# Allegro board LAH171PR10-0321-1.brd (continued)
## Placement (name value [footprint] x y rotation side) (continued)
PJP1  PAD-OPEN1x1m  [JUMP_43X39]  182.8 102.44 0 top
PJP2  PAD-OPEN1x1m  [JUMP_43X39]  184.01 98.56 0 top
PJP3  -  [JUMP_43X79]  227.9 90.05 180 top
PJP5  -  [JUMP_43X79]  31.19 114.13 90 top
PJP6  PAD-OPEN1x1m  [JUMP_43X39]  31.23 117.45 0 bottom
PJP8  PAD-OPEN 1x3m  [JUMP_43X118]  70.24 100.86 90 bottom
PJP12  PAD-OPEN1x1m  [JUMP_43X39]  145.02 131.58 0 top
PJP14  PAD-OPEN1x2m  [JUMP_43X79]  284.92 29.2 270 top
PJP17  PAD-OPEN1x2m  [JUMP_43X79]  288.54 76 270 top
PJP18  PAD-OPEN1x1m  [JUMP_43X39]  282.39 75.83 180 top
PJP19  PAD-OPEN1x1m  [JUMP_43X39]  293.67 59.38 0 top
PJP20  PAD-OPEN1x1m  [JUMP_43X39]  254.82 89.72 90 top
PJP22  PAD-OPEN1x1m  [JUMP_43X39]  253.23 99.34 270 top
PJP31  -  [JUMP_43X79]  258.02 43.4 180 top
PJP32  PAD-OPEN1x1m  [JUMP_43X39]  259.27 33.02 90 top
PJP33  PAD-OPEN1x1m  [JUMP_43X39]  257.2 36.44 90 top
PJP34  PAD-OPEN1x2m  [JUMP_43X79]  251.66 38.5 180 top
PJP35  PAD-OPEN1x1m  [JUMP_43X39]  195.72 40.64 180 top
PJP36  PAD-OPEN1x2m  [JUMP_43X79]  265.93 43.89 270 bottom
PJP37  PAD-OPEN1x1m  [JUMP_43X39]  255.94 80.35 180 top
PJP38  PAD-OPEN1x1m  [JUMP_43X39]  263.71 49.16 0 bottom
PJP39  PAD-OPEN1x3m  [JUMP_43X118]  255.27 50.41 270 top
PJP40  PAD-OPEN1x2m  [JUMP_43X79]  264.9 39.3 180 top
PJP41  PAD-OPEN1x3m  [JUMP_43X118]  256.98 86.6 270 bottom
PJP42  PAD-OPEN1x1m  [JUMP_43X39]  263.79 35.25 180 top
PJP100  PAD-OPEN 1x2m~D  [JUMP_43X79]  251.39 45.67 180 bottom
PJP101  PAD-OPEN 1x2m~D  [JUMP_43X79]  200.52 31.93 180 bottom
PJP102  -  [JUMP_43X118]  243.94 56.4 180 top
PJP103  -  [JUMP_43X118]  207.89 36.56 270 top
PJP200  -  [JUMP_43X118]  160.65 41.18 90 bottom
PJP201  -  [JUMP_43X39]  173.93 33.03 180 top
PJP202  PAD-OPEN 1x2m~D  [JUMP_43X79]  183 32.07 90 top
PJP301  PAD-OPEN 1x2m~D  [JUMP_43X79]  199.07 83.34 90 top
PJP302  -  [JUMP_43X118]  203.28 90.31 0 top
PJP401  -  [JUMP_43X79]  190.98 91.57 180 bottom
PJP403  PAD-OPEN1x1m  [JUMP_43X39]  201.78 95.46 180 bottom
PJP501  PAD-OPEN1x1m  [JUMP_43X39]  227.06 71.45 0 top
PJP502  PAD-OPEN1x1m  [JUMP_43X39]  235.39 76.17 270 top
PJP503  PAD-OPEN1x1m  [JUMP_43X39]  270.36 67.93 90 bottom
PJP504  PAD-OPEN1x1m  [JUMP_43X39]  270.47 64.07 0 bottom
PJP505  PAD-OPEN1x1m  [JUMP_43X39]  152.23 37.33 180 top
PJP506  PAD-OPEN1x1m  [JUMP_43X39]  144.93 37.58 90 top
PJP700  PAD-OPEN 4x4m  [JUMP_43X118-NPM]  90.47 41.05 0 bottom
PJP701  -  [JUMP_43X118]  147.72 116.99 0 top
PJP1604  -  [JUMP_43X79]  260.43 43.38 0 top
PJPA1  -  [JUMP_43X118]  200.4 128.43 90 top
PJPDC1  CVILU_CI0805M1HRC-NH  [CVILU_CI0805M1HRC-NH_5P-T]  66.08 126.47 270 bottom
PJPT1  -  [JUMP_43X118]  88.18 97.29 180 bottom
PL1  FBMJ4516HS720NT_2P  [TAIYO_FBMJ4516HS720NT_2P]  156.84 38.62 90 bottom
PL2  FBMJ4516HS720NT_2P  [TAIYO_FBMJ4516HS720NT_2P]  154.43 38.62 90 bottom
PL3  BLM15AG102SN1D_2P  [MURAT_BLM15AG102SN1D_2P]  50.99 124.24 90 top
PL4  -  [5A_Z80_0805_2P]  68.87 122.44 0 bottom
PL5  -  [5A_Z80_0805_2P]  68.87 124.22 0 bottom
PL100  1.5UH_9A_20%_7X7X3_M  [L_7X7X3_M_2P]  245.87 51.87 90 bottom
PL101  1.5UH_9A_20%_7X7X3_M  [L_7X7X3_M_2P]  207.55 31.72 90 bottom
PL201  1UH_11A_20%_7X7X3_M  [L_7X7X3_M_2P]  169.1 38.14 270 bottom
PL301  0.68UH_7.9A_20%_5X5X3_M  [L_5X5X3_M_2P]  201.54 84.51 90 bottom
PL402  1UH_PCMB042T-1R0MS_4.5A_20%  [CYNTE_PCMB042T-1R0MS_2P]  193.1 98.44 270 bottom
PL501  1UH_1277AS-H-1R0N-P2_3.3A_30%  [MAG_MLV-FY12N1R0M-O1L_2P]  229.01 77.67 0 top
PL700  1UH_PCMB051H-1R0MS_8A_20%  [CYNTE_PCMB051H-1R0MS_2P]  88.82 41.1 0 bottom
PL701  1UH_MMD-10DZ-1R0M-X1A_18A_20%  [MAG_MMD-10DZ-1R0M-X1A_2P]  108.53 41.1 270 bottom
PL800  5A_Z80_20M_0805_2P  [TAI-T_HCB2012KF-121T50_2P]  21.39 95.29 270 top
PL801  5A_Z80_20M_0805_2P  [TAI-T_HCB2012KF-121T50_2P]  23.17 95.29 270 top
PLA1  0.47UH_MMD05CZR47M_12A_20%  [MAG_MMD05CZR47M_4P]  197.7 109.72 180 bottom
PLH1  0.15UH_NA__36A_20%  [L_7X7X4_M]  158.21 120.15 180 bottom
PLH2  0.15UH_NA__36A_20%  [L_7X7X4_M]  171.15 120.21 180 bottom
PLH3  0.15UH_NA__36A_20%  [L_7X7X4_M]  181.58 120.25 180 bottom
PLH4  0.15UH_NA__36A_20%  [L_7X7X4_M]  187.93 122.06 270 bottom
PLH11  -  [5A_Z80_0805_2P]  150.16 124.27 0 top
PLH12  -  [5A_Z80_0805_2P]  149.64 120.6 0 top
PLH13  -  [5A_Z80_0805_2P]  149.64 122.44 0 top
PLT1  0.15UH_NA__36A_20%  [L_7X7X4_M]  107.54 85.59 0 bottom
PQ1  L2N7002DW1T1G 2N SC88-6  [DMN65D8LDW-7_SOT363-6]  73.09 115.72 270 top
PQ2  -  [FDV301N-G_SOT23-3]  52.23 118.69 270 top
PQ3  -  [MMST3904-7-F_SOT323-3]  50.28 117.93 90 top
PQ4  EMZB08P03V_EDFN3X3-8-5  [FDMC6679AZ_MLP8-5]  75.37 122.21 270 bottom
PQ5  AO3409 P-CHANNEL SOT-23  [AO3409_SOT23-3]  76.58 119.73 180 top
PQ6  2N7002KW 1N SOT323-3  [DMN65D8LW-7_SOT323-3]  103.63 127.64 0 top
PQ7  2N7002KW 1N SOT323-3  [DMN65D8LW-7_SOT323-3]  73.07 121.79 0 top
PQ8  2N7002KW 1N SOT323-3  [DMN65D8LW-7_SOT323-3]  103.56 128.98 180 top
PQ9  EMZB08P03V_P_DFN33-8-5  [FDMC6679AZ_MLP8-5]  72.51 124.19 90 bottom
PQ10  L2N7002DW1T1G 2N SC88-6  [DMN65D8LDW-7_SOT363-6]  98.86 130.61 90 top
PQ11  AO3409 P-CHANNEL SOT-23  [AO3409_SOT23-3]  96.02 134.64 270 top
PQ12  2N7002KW 1N SOT323-3  [DMN65D8LW-7_SOT323-3]  101 134.83 90 top
PQ13  -  [L2N7002WT1G_SC70-3]  35.24 125.48 180 top
PQ700  AON6354_N_DFN56-8-5  [Q_N_DFN56-8-5]  96.92 32.99 90 bottom
PQ701  AOE6936_DFN5X6E8-10  [AOE6930_DFN5X6E8-10]  115.37 30.93 90 top
PQ702  EMZB08P03V_EDFN3X3-8-5  [FDMC6679AZ_MLP8-5]  113.76 38.93 0 top
PQ703  2N7002KW 1N SOT323-3  [DMN65D8LW-7_SOT323-3]  141.07 33.91 90 top
PQ704  AON6354_N_DFN56-8-5  [Q_N_DFN56-8-5]  101.67 42.84 270 bottom
PQ800  EMZB08P03V_P_DFN33-8-5  [FDMC6679AZ_MLP8-5]  71.03 125.22 0 top
PQ801  EMZB08P03V_EDFN3X3-8-5  [FDMC6679AZ_MLP8-5]  76.05 123.51 0 top
PQ802  L2N7002DW1T1G 2N SC88-6  [DMN65D8LDW-7_SOT363-6]  102.09 71.2 0 top
PQ803  AO3409 P-CHANNEL SOT-23  [AO3409_SOT23-3]  96.4 71.3 270 top
PQ804  L2N7002DW1T1G 2N SC88-6  [DMN65D8LDW-7_SOT363-6]  107.88 75.4 270 top
PQ805  AO3409 P-CHANNEL SOT-23  [AO3409_SOT23-3]  110.97 71.51 270 top
PQ806  L2N7002DW1T1G 2N SC88-6  [DMN65D8LDW-7_SOT363-6]  110.72 76.59 0 top
PQ807  2N7002KW 1N SOT323-3  [DMN65D8LW-7_SOT323-3]  106.55 73.54 270 top
PQ808  L2N7002DW1T1G 2N SC88-6  [DMN66D0LDW-7_SOT363-6]  116.25 77.04 0 top
PQ809  L2N7002DW1T1G 2N SC88-6  [DMN66D0LDW-7_SOT363-6]  106.42 71.15 270 top
PQ810  L2N7002DW1T1G 2N SC88-6  [DMN66D0LDW-7_SOT363-6]  115.12 78.86 90 top
PQ811  L2N7002DW1T1G 2N SC88-6  [DMN66D0LDW-7_SOT363-6]  115 74.96 270 top
PQ812  2N7002KW 1N SOT323-3  [DMN65D8LW-7_SOT323-3]  111.95 74.75 90 top
PQ813  L2N7002DW1T1G 2N SC88-6  [DMN65D8LDW-7_SOT363-6]  108.96 77.15 90 top
PQ814  2N7002KW 1N SOT323-3  [DMN65D8LW-7_SOT323-3]  96.52 75.45 90 top
PQ3000  -  [L2N7002DW1T1G_SC88-6]  43.56 122.01 270 top
PR1  100K_0201_5%  [R_0201]  135.23 38.47 0 top
PR2  1K_0201_1%  [R_0201]  292.92 62.95 90 bottom
PR3  0_0402_5%  [R_0402]  50.1 124.2 90 top
PR4  2.2K_0201_5%  [R_0201]  47.81 124.11 90 top
PR5  33_0402_5%  [R_0402]  48.57 125.12 270 top
PR6  100K_0402_1%  [R_0402]  49.33 124.48 270 top
PR7  10K_0201_1%  [R_0201]  50.57 117.04 0 top
PR8  15K_0402_1%  [R_0402]  48.4 123.39 180 top
PR9  10M_0402_5%  [R_0402]  34.53 122.5 0 top
PR10  300K_0402_1%  [R_0402]  78.05 115.96 180 top
PR11  499K_0402_1%  [R_0402]  76.51 121.59 180 top
PR12  1M_0402_5%  [R_0402]  70.16 125.6 90 bottom
PR13  4.7K_0805_5%  [R_0805]  70.57 119.58 180 bottom
PR14  100K_0402_5%  [R_0402]  72.46 116.91 180 bottom
PR15  100K_0201_5%  [R_0201]  76.49 115.96 180 top
PR16  49.9K_0402_1%  [R_0402]  74.75 122.51 270 top
PR17  100K_0201_5%  [R_0201]  72.19 112.3 90 top
PR18  1M_0402_5%  [R_0402]  71.06 127.39 180 bottom
PR19  0_0402_5%  [R0402_0OHM]  72.96 113.43 270 top
PR20  0_0402_5%  [R0402_0OHM]  72.04 118.81 0 top
PR22  0_0402_5%  [R0402_0OHM]  100.88 125.74 0 top
PR24  100K_0201_5%  [R_0201]  73.67 118.87 0 top
PR25  0_0402_5%  [R0402_0OHM]  75.94 115.15 270 top
PR27  100K_0201_5%  [R_0201]  101.91 130.6 270 top
PR28  100K_0201_5%  [R_0201]  101.91 131.23 90 top
PR31  1M_0402_5%  [R_0402]  99.75 135.41 270 top
PR32  1M_0402_5%  [R_0402]  99.75 133.75 270 top
PR33  100K_0201_5%  [R_0201]  95.52 131.2 0 top
PR38  100_0402_5%  [R_0402]  136.58 34.41 90 top
PR39  100_0402_5%  [R_0402]  136.6 37.02 270 top
PR40  100_0402_5%  [R_0402]  136.6 37.82 90 top
PR41  0_0402_5%  [R_0402]  97.46 129.3 0 top
PR42  0_0402_5%  [R0402_0OHM]  97.46 128.47 0 top
PR43  0_0402_5%  [R_0402]  99.87 130.44 0 top
PR44  0_0402_5%  [R0402_0OHM]  100.08 125.74 180 top
PR45  10K_0201_1%  [R_0201]  100.68 129.68 180 top
PR46  0_0402_5%  [R0402_0OHM]  100.58 132.84 90 top
PR47  0_0402_5%  [R0402_0OHM]  101.79 129.25 270 top
PR49  0_0402_5%  [R0402_0OHM]  104.14 133.92 90 top
PR100  0_0603_5%  [R_0603]  249.49 48.08 90 bottom
PR102  499K_0402_1%  [R_0402]  243.4 44.02 180 bottom
PR103  499K_0402_1%  [R_0402]  243.39 44.78 180 bottom
PR104  0_0402_5%  [R0402_0OHM]  243.45 49.54 180 bottom
PR105  0_0402_5%  [R0402_0OHM]  243.44 48.76 180 bottom
PR106  4.7_1206_5%  [R_1206]  248.53 50.24 270 top
PR107  100K_0201_5%  [R_0201]  244.28 44.52 270 bottom
PR108  1K_0402_5%  [R_0402]  242.44 46.17 90 bottom
PR111  0_0603_5%  [R_0603]  201.3 34.28 0 top
PR112  4.7_1206_5%  [R_1206]  204.21 36.46 270 top
PR113  100K_0402_5%  [R_0402]  196.34 39.71 270 bottom
PR114  0_0402_5%  [R_0402]  197.21 39.89 0 top
PR116  1M_0402_1%  [R_0402]  198.13 40.08 180 bottom
PR117  1K_0402_5%  [R_0402]  198.99 39.89 0 top
PR119  0_0402_5%  [R0402_0OHM]  245.11 44.14 270 bottom
PR120  0_0402_5%  [R0402_0OHM]  244.28 42.3 90 bottom
PR202  4.7_1206_5%  [R_1206]  170.37 36.27 0 top
PR203  0_0603_5%  [R_0603]  173.54 37.92 180 top
PR204  102K_0402_1%  [R_0402]  176.78 40.35 270 bottom
PR205  0_0402_5%  [R_0402]  175.06 40.35 270 top
PR206  100K_0402_1%  [R_0402]  177.54 39.43 90 bottom
PR207  0_0402_5%  [R_0402]  175.89 39.43 90 top
PR208  0_0402_5%  [R_0402]  179 31.11 90 bottom
PR209  1M_0402_5%  [R_0402]  178.99 32.78 0 bottom
PR210  0_0402_5%  [R_0402]  178.11 31.11 90 bottom
PR212  1M_0402_5%  [R_0402]  178.14 32.82 180 bottom
PR302  1M_0402_1%  [R_0402]  195.73 88.72 270 top
PR303  4.7_1206_5%  [R_1206]  200.91 86.24 90 top
PR304  0_0603_5%  [R_0603]  196.72 84.08 270 bottom
PR306  22.1K_0402_1%  [R_0402]  197.8 91.13 270 bottom
PR307  0_0402_5%  [R_0402]  196.78 90.96 270 top
PR308  1K_0402_5%  [R_0402]  197.04 91.13 270 bottom
PR310  0_0402_5%  [R_0402]  196.02 90.04 90 top
PR311  29.4K_0402_1%  [R_0402]  196.27 90.24 180 bottom
PR312  15K_0402_1%  [R_0402]  196.55 87.8 90 top
PR402  0_0402_5%  [R_0402]  199.7 93.92 90 bottom
PR403  1M_0402_1%  [R_0402]  198.94 94.83 270 bottom
PR404  0_0402_5%  [R_0402]  198.12 93.91 90 bottom
PR405  4.7_0603_5%  [R_0603]  192.65 99.9 90 bottom
PR412  0_0402_5%  [R_0402]  197.29 101.69 270 bottom
PR413  10K_0402_1%  [R_0402]  201.43 100.85 180 bottom
PR414  10K_0402_1%  [R_0402]  201.51 100.02 180 bottom
PR415  10K_0402_1%  [R_0402]  199.77 100.77 90 bottom
PR416  10K_0402_1%  [R_0402]  200.59 99.2 0 bottom
PR421  0_0402_5%  [R_0402]  195.19 102.51 270 bottom
PR422  0_0402_5%  [R_0402]  195.18 100.78 0 bottom
PR425  0_0402_5%  [R_0402]  197.35 93.91 90 bottom
PR429  0_0402_5%  [R_0402]  196.59 93.91 90 bottom
PR501  20K_0402_1%  [R_0402]  233.74 75.84 270 top
PR502  4.7_0603_5%  [R_0603]  227.52 78.12 270 top
PR504  0_0402_5%  [R_0402]  226.37 74.57 270 top
PR505  1M_0402_1%  [R_0402]  227.26 73.66 90 top
PR506  10K_0402_1%  [R_0402]  232.9 74.11 0 top
PR509  1M_0402_1%  [R_0402]  264.83 66.68 270 bottom
PR510  10.2K_0402_1%  [R_0402]  267.51 61.85 180 bottom
PR511  0_0402_5%  [R_0402]  266.75 67.62 180 bottom
PR512  5.1K_0402_1%  [R_0402]  269.23 61.02 180 bottom
PR513  0_0402_5%  [R_0402]  151.91 35.8 180 top
PR514  1M_0402_1%  [R_0402]  151 34.09 0 top
PR515  21.5K_0402_1%  [R_0402]  144.31 35.06 0 top
PR516  10K_0402_1%  [R_0402]  144.32 33.22 0 top
PR517  100K_0402_5%  [R_0402]  230.63 70.67 90 top
PR700  0.01_1206_1%  [R_1206_4P-D]  85.97 43.71 270 bottom
PR701  1_0603_1%  [R_0603]  126.85 42.8 270 bottom
PR702  1_0603_1%  [R_0603]  125.6 42.81 270 bottom
PR703  0_0603_5%  [R_0603]  130.27 39.62 180 bottom
PR704  2.2_0603_5%  [R_0603]  123.44 42.49 270 bottom
PR705  442K_0402_1%  [R_0402]  129.65 38.6 180 bottom
PR706  100K_0402_5%  [R_0402]  128.74 37.84 0 bottom
PR707  4.7_0603_5%  [R_0603]  121.34 40.14 180 bottom
PR708  2_1206_5%  [R_1206]  132.71 39.57 90 top
PR709  0_0402_5%  [R0402_0OHM]  129.79 37.03 180 top
PR710  100K_0201_1%  [R_0201]  140.68 34.76 90 top
PR711  0.005_1206_1%  [R_1206_4P-D]  114.99 36.78 180 top
PR712  0_0402_5%  [R_0402]  140.01 35.38 270 top
PR713  0_0402_5%  [R0402_0OHM]  129.65 36.09 180 bottom
PR714  2.2_0603_5%  [R_0603]  119.57 36.59 90 bottom
PR715  0_0402_5%  [R0402_0OHM]  129.65 35.33 180 bottom
PR716  154K_0402_1%  [R_0402]  141.57 32.27 270 top
PR717  4.7_1206_5%  [R_1206]  101.55 35.1 180 top
PR718  4.7_1206_5%  [R_1206]  106.55 34.17 90 top
PR719  0_0402_5%  [R0402_0OHM]  129.65 34.57 180 bottom
PR720  1M_0402_1%  [R_0402]  142.44 32.24 270 top
PR721  0_0402_5%  [R0402_0OHM]  120.53 34.49 180 bottom
PR722  0_0402_5%  [R0402_0OHM]  140.75 32.91 270 top
PR723  100K_0402_1%  [R_0402]  127.01 32.81 270 top
PR724  100K_0402_1%  [R_0402]  127.77 31.9 90 top
PR725  316K_0402_1%  [R_0402]  127.86 32.65 270 bottom
PR726  100K_0201_1%  [R_0201]  130 33.02 180 bottom
PR727  0_0402_5%  [R0402_0OHM]  128.69 32.05 90 bottom
PR728  0_0402_5%  [R_0402]  127 32.66 270 bottom
PR729  0_0402_5%  [R0402_0OHM]  124.37 32.65 270 top
PR731  0_0402_5%  [R0402_0OHM]  124.43 32.65 270 bottom
PR733  1_0603_1%  [R_0603]  121.13 33.23 180 bottom
PR734  1_0603_1%  [R_0603]  122.8 30.05 180 bottom
PR735  0_0402_5%  [R_0402]  145.32 30.21 180 top
PR736  0_0402_5%  [R0402_0OHM]  144.41 31.04 0 top
PR737  0_0402_5%  [R0402_0OHM]  144.41 31.86 0 top
PR738  100_0402_5%  [R_0402]  122.65 32.65 270 bottom
PR739  100K_0201_1%  [R_0201]  150.25 32.67 0 top
PR740  0_0402_5%  [R0402_0OHM]  153.36 30.26 90 top
PR741  0_0402_5%  [R0402_0OHM]  149.37 30.3 90 top
PR743  0_0402_5%  [R0402_0OHM]  125.13 32.65 270 top
PR744  100K_0201_1%  [R_0201]  153.3 31.95 90 top
PR745  0_0402_5%  [R_0402]  129.59 33.71 180 bottom
PR746  0_0402_5%  [R_0402]  129.79 36.14 180 top
PR800  422K_0402_1%  [R_0402]  82.57 106.16 90 bottom
PR801  300K_0402_1%  [R_0402]  100.2 72.16 270 top
PR802  300K_0402_1%  [R_0402]  114.8 71.05 90 top
PR803  499K_0402_1%  [R_0402]  71.98 122.93 0 top
PR804  499K_0402_1%  [R_0402]  77.45 121.61 0 top
PR805  1.8M_0402_1%  [R_0402]  81.74 107.07 270 bottom
PR806  1K_0201_1%  [R_0201]  81.02 106.73 270 bottom
PR807  100K_0402_5%  [R_0402]  100.19 70.43 0 top
PR808  100K_0201_5%  [R_0201]  114.77 72.72 0 top
PR809  102K_0402_1%  [R_0402]  81.47 109.75 270 bottom
PR810  100K_0201_5%  [R_0201]  105.19 70.75 270 top
PR811  49.9K_0402_1%  [R_0402]  73.76 123.92 0 top
PR812  49.9K_0402_1%  [R_0402]  109.29 73.04 180 top
PR813  100K_0201_5%  [R_0201]  110.42 81.33 270 top
PR814  0_0402_5%  [R0402_0OHM]  111.36 79.39 180 top
PR815  37.4K_0402_1%  [R_0402]  79.15 104.8 270 bottom
PR816  0_0402_5%  [R0402_0OHM]  110.71 74.48 90 top
PR817  24.9K_0402_1%  [R_0402]  78.24 104.04 180 bottom
PR818  0_0402_5%  [R0402_0OHM]  106.03 75.26 0 top
PR819  100K_0201_5%  [R_0201]  111.29 73.8 180 top
PR820  0_0402_5%  [R0402_0OHM]  106.93 80.41 270 top
PR821  100K_0201_5%  [R_0201]  104.61 71.94 270 top
PR822  100K_0201_5%  [R_0201]  105.19 71.36 90 top
PR823  100K_0402_5%  [R_0402]  20.07 92.85 180 top
PR824  100K_0201_5%  [R_0201]  114.4 77.92 180 top
PR825  100K_0201_5%  [R_0201]  111.02 80.97 0 top
PR826  0_0402_5%  [R0402_0OHM]  112.17 79.37 90 top
PR827  0_0402_5%  [R0402_0OHM]  113.09 76.45 90 top
PR828  100K_0201_5%  [R_0201]  113.85 81.65 270 top
PR829  0_0402_5%  [R0402_0OHM]  117.1 75.89 180 top
PR830  100K_0201_5%  [R_0201]  115.12 77.44 90 top
PR831  499K_0402_1%  [R_0402]  75.04 112.85 0 bottom
PR832  102K_0402_1%  [R_0402]  77.66 113.69 270 bottom
PR833  100K_0201_5%  [R_0201]  114.7 76.78 0 top
PR834  0_0402_5%  [R_0402]  117.8 79.89 180 top
PR835  47K_0402_1%  [R_0402]  76.74 106.98 90 bottom
PR836  0_0402_5%  [R0402_0OHM]  108.91 79.51 180 top
PR838  100K_0201_5%  [R_0201]  107.69 72.69 270 top
PR839  100K_0201_5%  [R_0201]  107.06 72.69 270 top
PR840  0_0402_5%  [R0402_0OHM]  106.17 76.96 90 top
PR841  0_0402_5%  [R_0402]  116.07 80.73 270 top
PR842  97.6K_0402_1%  [R_0402]  75.95 113.74 180 bottom
PR843  37.4K_0402_1%  [R_0402]  79.43 112.77 90 bottom
PR844  0_0402_5%  [R0402_0OHM]  109.28 71.4 270 top
PR845  0_0402_5%  [R_0402]  109.29 72.21 180 top
PR846  10K_0201_1%  [R_0201]  104.33 77.52 270 top
PR851  100K_0201_5%  [R_0201]  104.49 70.41 180 top
PR852  100K_0201_5%  [R_0201]  111.05 80.12 180 top
PR853  0_0402_5%  [R0402_0OHM]  103.64 77.8 180 top
PR854  0_0402_5%  [R0402_0OHM]  105.29 75.26 180 top
PR855  10K_0201_1%  [R_0201]  102.81 74.6 0 top
PR856  0_0402_5%  [R_0402]  101.91 78.7 270 top
PR857  0_0402_5%  [R_0402]  103.64 78.62 180 top
PR858  0_0402_5%  [R0402_0OHM]  101.1 72.91 180 top
PR859  0_0402_5%  [R0402_0OHM]  99.55 76.27 0 top
PR861  0_0402_5%  [R0402_0OHM]  99.42 74.55 0 top
PR862  100K_0402_5%  [R_0402]  77.02 127.48 90 top
PR865  100K_0402_5%  [R_0402]  103.83 131.96 180 top
PR866  0_0402_5%  [R_0402]  41.75 121.65 270 top
PR870  499K_0402_1%  [R_0402]  76.89 109.34 90 bottom
PR871  22_0805_5%  [R_0805]  83.73 113.65 270 top
PR872  22_0805_5%  [R_0805]  83.45 110.5 0 top
PR1616  0_0201_5%  [R_0201]  156.71 129.19 0 bottom
PR1617  0_0201_5%  [R_0201]  156.71 128.61 0 bottom
PR1618  0_0201_5%  [R_0201]  167.75 129.74 90 bottom
PR1619  0_0201_5%  [R_0201]  167.75 129.14 270 bottom
PR1620  0_0201_5%  [R_0201]  100.35 82.64 90 bottom
PR1621  0_0201_5%  [R_0201]  100.94 82.64 90 bottom
PR1622  0_0201_5%  [R_0201]  193.99 118.68 0 bottom
PR1623  0_0201_5%  [R_0201]  193.99 118.11 0 bottom
PR1624  0_0201_5%  [R_0201]  187.42 129.77 90 bottom
PR1625  0_0201_5%  [R_0201]  187.42 129.11 270 bottom
PR1626  0_0201_5%  [R_0201]  177.74 129.61 90 bottom
PR1627  0_0201_5%  [R_0201]  177.74 129 270 bottom
PR1648  0_0402_5%  [R_0402]  196.15 91.06 90 bottom
PR1649  0_0402_5%  [R0402_0OHM]  195.38 91.97 270 bottom
PR1650  100_0402_5%  [R_0402]  198.69 91.89 270 bottom
PR1651  0_0402_5%  [R0402_0OHM]  196.71 92.91 0 bottom
PR1652  0_0402_5%  [R0402_0OHM]  117.8 80.66 180 top
PR1708  200K_0402_1%  [R_0402]  199 100.78 90 bottom
PR1711  100K_0402_5%  [R_0402]  193.1 88.48 270 bottom
PR1712  0_0402_5%  [R_0402]  192.27 87.56 90 bottom
PR1713  0_0402_5%  [R_0402]  231.52 70.67 90 top
PR3001  0_0402_5%  [R_0402]  46.41 122.45 270 top
PR3002  200K_0402_1%  [R_0402]  41.84 122.43 90 top
PR3003  300K_0402_1%  [R_0402]  42.6 122.55 90 top
PR3004  200K_0402_1%  [R_0402]  37.32 124.91 0 top
PR3005  402K_0402_1%  [R_0402]  37.32 124.15 0 top
PR3006  0_0402_5%  [R_0402]  39.68 116.77 90 top
PR3007  237K_0402_1%  [R_0402]  38.97 119.07 0 top
PR3008  43.2K_0402_1%  [R_0402]  38.97 119.83 0 top
PR3009  14.7K_0402_1%  [R_0402]  37.05 120.61 270 top
PR3010  147K_0402_1%  [R_0402]  36.19 120.61 270 top
PR3011  43.2K_0402_1%  [R_0402]  36.19 121.35 90 top
PR3012  1K_0201_1%  [R_0201]  40.41 123.73 0 top
PR3013  1K_0201_1%  [R_0201]  40.38 120.61 0 top
PRA1  2_0603_5%  [R_0603]  193.54 119.83 90 bottom
PRA2  3.9_0603_1%  [R_0603]  199.19 120.91 90 top
PRA3  4.7_1206_5%  [R_1206]  198.5 110.82 90 top
PRH1  2_0603_5%  [R_0603]  156.97 130.38 0 top
PRH2  2_0603_5%  [R_0603]  178.75 131.46 90 bottom
PRH3  3.9_0603_1%  [R_0603]  181.05 131.43 90 bottom
PRH4  3.9_0603_1%  [R_0603]  162.81 131.32 45 top
PRH5  10_0402_1%  [R_0402]  176.41 120.47 180 top
PRH6  10_0402_1%  [R_0402]  153.41 120.23 270 top
PRH7  4.7_1206_5%  [R_1206]  181.41 121.42 90 top
PRH8  4.7_1206_5%  [R_1206]  162.24 122.88 0 top
PRH9  2_0603_5%  [R_0603]  189.35 131.58 90 bottom
PRH10  3.9_0603_1%  [R_0603]  191.63 131.63 90 bottom
PRH11  2_0603_5%  [R_0603]  169.03 131.46 0 top
PRH12  3.9_0603_1%  [R_0603]  171.4 131.37 90 bottom
PRH13  10_0402_1%  [R_0402]  187.84 115.52 180 top
PRH14  10_0402_1%  [R_0402]  166.63 121.3 180 top
PRH15  4.7_1206_5%  [R_1206]  193.54 124.98 270 top
PRH16  4.7_1206_5%  [R_1206]  172.08 121.55 90 top
PRT1  2_0603_5%  [R_0603]  96.96 83.13 90 bottom
PRT2  3.9_0603_1%  [R_0603]  98.31 86.63 180 bottom
PRT3  10_0402_1%  [R_0402]  111.26 84.59 180 top
PRT4  4.7_1206_5%  [R_1206]  108.14 86.62 180 top
PRZ1  100_0201_1%  [R_0201]  163.7 113.04 180 bottom
PRZ3  12K_0402_1%  [R_0402]  94.23 103.11 0 bottom
PRZ4  7.5K_0603_1%  [R_0603]  193.67 113.13 0 bottom
PRZ5  10_0402_1%  [R_0402]  94.23 103.94 0 bottom
PRZ6  499_0402_1%  [R_0402]  94.42 96.19 0 bottom
PRZ7  100_0402_1%  [R_0402]  94.42 97.02 0 bottom
PRZ8  45.3_0402_1%  [R_0402]  94.42 97.84 0 bottom
PRZ9  45.3_0402_1%  [R_0402]  94.42 98.67 0 bottom
PRZ11  0_0402_5%  [R0402_0OHM]  95.37 106.54 0 bottom
PRZ12  1.21K_0402_1%  [R_0402]  97.09 107.37 0 bottom
PRZ13  0_0402_5%  [R0402_0OHM]  95.39 107.35 90 bottom
PRZ14  1.74K_0402_1%  [R_0402]  97.09 108.19 0 bottom
PRZ15  28K_0402_1%  [R_0402]  96.83 102.1 0 top
PRZ16  100_0402_1%  [R_0402]  97.81 96.19 180 bottom
PRZ17  100_0201_1%  [R_0201]  164.9 113.04 180 bottom
PRZ18  2.21K_0402_1%  [R_0402]  97.09 108.95 0 bottom
PRZ19  49.9_0402_1%  [R_0402]  98.45 98.79 180 bottom
PRZ20  10K_0402_1%  [R_0402]  96.9 101.14 0 bottom
PRZ21  0_0402_5%  [R0402_0OHM]  98.45 97.97 180 bottom
PRZ22  12K_0402_1%  [R_0402]  96.83 103.05 0 top
PRZ23  10_0402_1%  [R_0402]  98.45 97.14 180 bottom
PRZ24  1.5K_0402_1%  [R_0402]  95.89 104.69 90 bottom
PRZ26  38.3K_0402_1%  [R_0402]  97.75 100.32 180 top
PRZ27  0_0402_5%  [R0402_0OHM]  100.4 107.63 270 bottom
PRZ28  0_0402_5%  [R0402_0OHM]  98.45 99.62 180 bottom
PRZ29  100_0201_1%  [R_0201]  152.17 112.02 0 bottom
PRZ30  0_0402_5%  [R0402_0OHM]  98.62 95.03 90 bottom
PRZ31  0_0402_5%  [R0402_0OHM]  100.39 108.45 0 bottom
PRZ32  2.05K_0402_1%  [R_0402]  103.01 107.63 270 bottom
PRZ37  2.55K_0402_1%  [R_0402]  101.23 95.03 90 bottom
PRZ38  0_0402_5%  [R0402_0OHM]  98.61 94.22 0 bottom
PRZ39  100_0201_1%  [R_0201]  153.44 112.02 0 bottom
PRZ40  49.9_0402_1%  [R_0402]  102.94 107.54 90 top
PRZ41  27K_0402_1%  [R_0402]  100.4 107.57 270 top
PRZ42  3.65K_0402_1%  [R_0402]  104.72 107.54 90 top
PRZ43  49.9_0402_1%  [R_0402]  98.62 98.56 180 top
PRZ44  33.2K_0402_1%  [R_0402]  103.01 95.95 270 bottom
PRZ45  1K_0402_1%  [R_0402]  102.96 106.67 180 top
PRZ46  1K_0402_1%  [R_0402]  99.44 98.58 270 top
PRZ47  3.65K_0402_1%  [R_0402]  98.62 96.85 180 top
PRZ48  30.1K_0402_1%  [R_0402]  103.83 107.63 270 bottom
PRZ49  13K_0402_1%  [R_0402]  103.83 95.95 270 bottom
PRZ50  75K_0402_1%  [R_0402]  103.83 109.28 270 bottom
PRZ51  1K_0402_1%  [R_0402]  110.39 95.94 180 bottom
PRZ52  75K_0402_1%  [R_0402]  104.88 93.67 180 bottom
PRZ53  90.9K_0603_1%  [R_0603]  106.94 110.12 270 top
PRZ54  165K_0402_1%  [R_0402]  105.56 108.45 180 bottom
PRZ55  165K_0402_1%  [R_0402]  105.8 92.83 180 bottom
PRZ56  90.9K_0603_1%  [R_0603]  108.15 110.12 270 top
PRZ57  1K_0402_1%  [R_0402]  110.19 103.18 180 bottom
PRZ58  90.9K_0603_1%  [R_0603]  109.36 110.12 270 top
PRZ59  61.9K_0603_1%  [R_0603]  105.8 93.84 0 bottom
PRZ60  90.9K_0603_1%  [R_0603]  110.56 110.12 270 top
PRZ61  2.2_0603_5%  [R_0603]  110.82 101.21 180 bottom
PRZ62  10.5K_0402_1%  [R_0402]  109.47 100.19 0 bottom
PRZ63  25.5K_0402_1%  [R_0402]  107.13 100.09 180 top
PRZ64  2.15K_0402_1%  [R_0402]  107.01 109.09 270 bottom
PRZ65  1K_0402_1%  [R_0402]  107.26 106.74 270 bottom
PRZ66  102K_0402_1%  [R_0402]  109.34 103.43 0 top
PRZ67  4.3K_0402_1%  [R_0402]  109.34 102.6 0 top
PRZ68  24.9K_0402_1%  [R_0402]  109.34 101.78 0 top
PRZ69  97.6K_0402_1%  [R_0402]  109.34 100.95 0 top
PRZ70  97.6K_0402_1%  [R_0402]  109.34 100.13 0 top
PRZ71  2.15K_0402_1%  [R_0402]  108.09 94.17 270 bottom
PRZ72  2.15K_0402_1%  [R_0402]  107.95 109.12 270 bottom
PRZ73  1K_0402_1%  [R_0402]  108.23 95.94 180 bottom
PRZ74  1.05K_0402_1%  [R_0402]  108.91 106.74 270 bottom
PRZ75  2.15K_0402_1%  [R_0402]  108.82 108.46 0 bottom
PRZ76  210_0402_1%  [R_0402]  110.56 106.74 270 bottom
PRZ77  1K_0402_1%  [R_0402]  110.39 98.41 180 bottom
PRZ78  0_0402_5%  [R0402_0OHM]  157.23 125.17 180 bottom
PRZ79  0_0402_5%  [R0402_0OHM]  102.99 82.89 270 top
PRZ80  2.15K_0402_1%  [R_0402]  110.54 108.46 0 bottom
PRZ81  110_0402_1%  [R_0402]  109.47 96.76 0 bottom
PRZ82  8.66K_0402_1%  [R_0402]  157.23 126.06 180 bottom
PRZ83  8.66K_0402_1%  [R_0402]  104.77 82.89 270 top
PU2  RT9058-33GX_SOT89-3  [AP2204R-5P0TRG1_SOT89-3]  79.79 110.37 180 top
PU3  MC74VHC1G08DFT2G_SC70-5  [TC7SH08FU_SSOP5]  99.41 126.8 0 top
PU100  -  [SY8288BRAC_QFN20_3X3]  247.93 48.21 180 bottom
PU102  SYV828CRAC_QFN20_3X3  [SY8288CRAC_QFN20_3X3]  200.11 34.76 90 bottom
PU200  -  [SY8210AQVC_QFN19_4X3]  177.06 35.3 90 bottom
PU301  SY8286RAC_QFN20_3X3  [SY8288RAC_QFN20_3X3]  196.92 85.46 90 bottom
PU401  -  [SY8057BQDC_QFN16_3X3]  196.17 97.15 0 bottom
PU501  -  [RT8097ALGE_SOT23-6]  231.39 75.41 180 top
PU502  -  [EM1109V-AD_DFN3308-8_3X3]  268.85 63.24 180 bottom
PU503  -  [EM1109V-AD_DFN3308-8_3X3]  146.63 35.77 270 top
PU700  ISL9538BHRTZ-T TQFN 32P CHARGER ES  [ISL88738HRTZ-T_TQFN32_4X4]  122.7 35.36 0 bottom
PU701  MC74VHC1G08DFT2G_SC70-5  [TC7SH08FU_SSOP5]  150.38 31.75 270 top
PU800  -  [AS393MMTR-G1_MSOP8]  79.96 106.8 90 bottom
PU801  MC74VHC1G08DFT2G_SC70-5  [TC7SH08FU_SSOP5]  103.39 75.51 90 top
PU3000  -  [AZV3002RL-7_U-FLGA8_1P65X1P65]  40.3 122.78 180 top
PUA1  -  [NCP302045MNTWG_PQFN33_5X5]  196.86 119.42 0 bottom
PUH1  -  [NCP302045MNTWG_PQFN33_5X5]  159.58 129.81 0 bottom
PUH2  -  [NCP302045MNTWG_PQFN33_5X5]  169.62 129.79 0 bottom
PUH3  -  [NCP302045MNTWG_PQFN33_5X5]  179.55 129.87 0 bottom
PUH4  -  [NCP302045MNTWG_PQFN33_5X5]  189.2 129.94 0 bottom
PUT1  -  [NCP302045MNTWG_PQFN33_5X5]  99.86 85.18 90 bottom
PUZ1  NCP81215DPA0MNTXG_QFN52_6X6  [NCP81215MNTXG_QFN52_6X6]  101.13 104.18 270 bottom
QE2  L2N7002DW1T1G_SC88-6  [DMN65D8LDW-7_SOT363-6]  254.33 108.85 180 top
QE3  -  [LMBT3904WT1G_SC70-3]  146.03 97.23 180 top
QE4  -  [LMBT3904WT1G_SC70-3]  284.85 92.53 90 top
QE5  -  [LMBT3904WT1G_SC70-3]  265.36 34.23 0 bottom
QE6  -  [LMBT3904WT1G_SC70-3]  146.38 118.44 180 bottom
QE7  -  [LMBT3904WT1G_SC70-3]  129.6 40.91 180 bottom
QE11  -  [L2N7002WT1G_SC-70-3]  286.5 96.72 270 top
QE12  -  [L2N7002WT1G_SC-70-3]  269.04 108.97 0 top
QE15  -  [LP2301ALT1G_SOT23-3]  281.64 100.78 90 top
QE17  -  [L2N7002WT1G_SC-70-3]  283.4 103.52 180 top
QE20  -  [L2N7002WT1G_SC-70-3]  266.86 88.95 0 top
QH4  L2N7002DW1T1G_SC88-6  [DMN65D8LDW-7_SOT363-6]  228.66 123.22 90 bottom
QH6  -  [L2N7002WT1G_SC-70-3]  249.3 117.74 0 top
QH7  -  [LP2301ALT1G_SOT23-3]  245.99 116.7 0 top
QH8  L2N7002DW1T1G_SC88-6  [DMN65D8LDW-7_SOT363-6]  249.87 103.66 270 top
QI2  -  [L2N7002WT1G_SC-70-3]  75.66 102.15 270 bottom
QL1  L2N7002DW1T1G_SC88-6  [DMN65D8LDW-7_SOT363-6]  290.12 115.49 270 top
QN1  L2N7002DW1T1G_SC88-6  [DMN65D8LDW-7_SOT363-6]  253.8 42.79 270 bottom
QN6  -  [L2N7002WT1G_SC-70-3]  251.2 31.41 180 top
QR1  -  [L2N7002WT1G_SC-70-3]  297.75 27 90 top
QT1  -  [DMN66D0LDW-7_SOT363-6]  64.12 97.96 0 top
QV1  -  [AO6405_TSOP6]  133.16 135.67 180 top
QV2  -  [L2N7002WT1G_SC-70-3]  125.35 135.13 0 top
QV7  -  [L2N7002WT1G_SC-70-3]  115.37 134.44 270 top
QV8  -  [LP2301ALT1G_SOT23-3]  122.83 134.81 90 top
QV18  -  [MMBT3906H_SOT23-3]  145.54 123.29 180 top
QV19  -  [LMBT3904WT1G_SC70-3]  135.25 121.61 270 top
QV20  -  [MMBT3906H_SOT23-3]  139.42 125.23 270 top
QV21  -  [LMBT3904WT1G_SC70-3]  133.72 121.61 90 top
QZ1  -  [LP2301ALT1G_SOT23-3]  131.17 126.45 180 top
QZ3  LMUN5111T1G_SC70-3  [DDTA114EUA-7-F_SOT323-3]  260.31 111.71 270 top
QZ7  L2N7002DW1T1G_SC88-6  [DMN65D8LDW-7_SOT363-6]  282.7 85.56 270 top
QZ8  S TR BSS138W 1N SOT-323-3  [L2N7002WT1G_SC-70-3]  275.84 74.37 270 top
QZ15  -  [BSS138W-7-F_SOT323-3]  280.79 88.21 270 top
QZ17  L2N7002DW1T1G_SC88-6  [DMN65D8LDW-7_SOT363-6]  274.83 44.45 90 bottom
QZ18  L2N7002DW1T1G_SC88-6  [DMN65D8LDW-7_SOT363-6]  280.6 46.19 270 bottom
QZ19  S TR BSS138W 1N SOT-323-3  [L2N7002WT1G_SC-70-3]  279.4 74.37 180 top
QZ21  -  [LMBT3904WT1G_SC70-3]  259.97 109.17 270 top
QZ24  -  [BSS138W-7-F_SOT323-3]  255.58 87.77 270 top
QZ38  -  [LP2301ALT1G_SOT23-3]  282.89 123.04 180 top
RA3  0_0603_5%  [R0603_0OHM]  292.29 60.79 90 top
RA5  2.2K_0402_5%  [R_0402]  296.43 32.84 180 bottom
RA6  2.2K_0402_5%  [R_0402]  296.43 31 180 bottom
RA7  16.2_0402_1%  [R_0402]  288.29 47.34 270 top
RA8  16.2_0402_1%  [R_0402]  287.02 47.34 270 top
RA9  33_0402_5%  [R_0402]  279.57 52.98 0 top
RA12  1K_0402_5%  [R_0402]  278.76 49.12 270 top
RA13  1K_0402_5%  [R_0402]  278.01 49.17 180 top
RA14  22_0402_5%  [R_0402]  279.57 56.09 0 top
RA17  33_0402_5%  [R_0402]  280.49 55.14 180 top
RA18  10K_0402_5%  [R_0402]  278 59.85 270 top
RA35  0_0402_5%  [R0402_0OHM]  283.14 46.95 270 top
RA36  0_0402_5%  [R0402_0OHM]  289.94 61.03 90 top
RA37  0_0402_5%  [R0402_0OHM]  293.67 53.99 0 top
RA44  100K_0402_5%  [R_0402]  290.11 50.76 0 top
RA45  10K_0402_5%  [R_0402]  278.01 50.89 180 top
RA48  0_0402_5%  [R0402_0OHM]  278 61.5 270 top
RA50  0_0402_5%  [R_0402]  276.98 57.99 90 top
RA51  10K_0402_5%  [R_0402]  279.52 49.12 270 top
RA52  100K_0402_5%  [R_0402]  277.8 56.92 0 top
RA53  0_0402_5%  [R0402_0OHM]  285.05 46.96 270 top
RA54  0_0402_5%  [R_0402]  285.87 46.96 270 top
RA57  4.7K_0402_5%  [R_0402]  289.05 47.34 270 top
RA58  4.7K_0402_5%  [R_0402]  287.92 45.62 180 top
RA59  100K_0402_1%  [R_0402]  284.22 46.04 90 top
RA60  200K_0402_1%  [R_0402]  283.54 48.84 180 top
RC1  24.9_0402_1%  [R_0402]  174.05 115.4 270 top
RC2  24.9_0402_1%  [R_0402]  170.95 78.67 90 top
RC5  121_0402_1%  [R_0402]  177.03 81.37 270 bottom
RC6  75_0402_1%  [R_0402]  177.92 81.37 270 bottom
RC7  100_0402_1%  [R_0402]  178.75 81.37 270 bottom
RC66  20_0402_5%  [R_0402]  178.87 109.05 270 bottom
RC71  1K_0402_5%  [R_0402]  181.05 90.37 180 bottom
RC74  10K_0402_5%  [R_0402]  225.23 120.46 90 top
RC75  10K_0402_5%  [R_0402]  242.69 114.93 90 top
RC78  60.4_0402_1%  [R_0402]  177.55 90.37 180 bottom
RC79  49.9_0402_1%  [R_0402]  125.38 101.17 0 bottom
RC80  1K_0402_5%  [R_0402]  177.1 114.42 90 top
RC83  1K_0402_5%  [R_0402]  125.38 101.99 0 bottom
RC84  499_0402_1%  [R_0402]  127.11 101.61 0 bottom
RC114  49.9_0402_1%  [R_0402]  128 99.2 180 bottom
RC115  2.2K_0402_5%  [R_0402]  88.6 129.22 90 top
RC121  1K_0402_5%  [R_0402]  76.46 135.52 180 top
RC122  0_0402_5%  [R_0402]  76.53 136.34 180 top
RC124  1K_0402_5%  [R_0402]  85.07 133.52 90 top
RC126  1K_0402_5%  [R_0402]  79.56 134.07 270 top
RC127  1K_0402_5%  [R_0402]  247.84 108.42 270 top
RC128  1K_0402_5%  [R_0402]  231.33 133.16 90 bottom
RC129  0_0402_5%  [R_0402]  208.87 112.98 180 top
RC132  150_0402_5%  [R_0402]  78.74 134.07 270 top
RC133  1.5K_0402_5%  [R_0402]  91.31 134.39 270 top
RC135  51_0402_5%  [R_0402]  122.79 102.56 0 top
RC136  51_0402_5%  [R_0402]  127.44 102.36 90 bottom
RC137  3K_0402_5%  [R_0402]  90.08 129.87 270 bottom
RC138  51_0402_5%  [R_0402]  75.24 133.6 90 top
RC139  51_0402_5%  [R_0402]  124.15 100.47 180 top
RC140  100_0201_1%  [R_0201]  155.89 112.66 180 bottom
RC141  100_0201_1%  [R_0201]  154.68 112.66 180 bottom
RC143  0_0402_5%  [R0402_0OHM]  121.8 99.77 180 top
RC144  0_0402_5%  [R_0402]  87.77 129.17 180 top
RC152  56.2_0402_1%  [R_0402]  117.61 104.09 180 top
RC153  220_0402_5%  [R_0402]  116.7 104.98 0 top
RC157  100_0402_5%  [R_0402]  118.55 103.25 90 top
RC166  1K_0402_5%  [R_0402]  120.89 100.76 0 top
RC168  20_0402_5%  [R_0402]  127.81 104.53 0 bottom
RC169  0_0402_5%  [R0402_0OHM]  175.83 115.34 270 top
RC171  0_0402_5%  [R_0402]  129.27 81.54 0 top
RC177  30_0402_5%  [R_0402]  167.03 98.43 0 top
RC178  0_0402_5%  [R0402_0OHM]  177.32 112.15 0 bottom
RC179  0_0402_5%  [R0402_0OHM]  177.32 112.98 0 bottom
RC181  1K_0402_5%  [R_0402]  135.14 101.8 180 top
RC216  0_0603_1%  [R0603_0OHM]  87.04 131.11 0 top
RC217  0_0402_5%  [R_0402]  77.53 134.39 270 top
RC218  150_0402_5%  [R_0402]  76 133.6 90 top
RC219  10K_0402_5%  [R_0402]  76.77 133.47 90 top
RC221  49.9_0201_1%  [R_0201]  154.77 112.02 0 bottom
RC228  0_0402_5%  [R0402_0OHM]  121.8 101.55 180 top
RC229  0_0402_5%  [R0402_0OHM]  121.36 103.58 180 top
RC230  0_0402_5%  [R0402_0OHM]  121.36 102.56 180 top
RC239  0_0402_5%  [R_0402]  124.09 97.23 180 top
RC240  0_0402_5%  [R_0402]  124.09 98.12 180 top
RC241  1.5K_0402_5%  [R_0402]  88.18 134.36 270 top
RC304  0_0402_5%  [R0402_0OHM]  177.92 114.42 90 top
RC314  0_0402_5%  [R0402_0OHM]  78.28 132.34 0 top
RC315  0_0402_5%  [R0402_0OHM]  128 100.28 180 bottom
RC319  0_0402_5%  [R0402_0OHM]  127.81 105.29 0 bottom
RC321  1K_0402_5%  [R_0402]  135.11 100.28 0 top
RC322  1K_0402_5%  [R_0402]  124.09 93.67 180 top
RC323  1K_0402_5%  [R_0402]  134.22 97.23 0 top
RC324  1K_0402_5%  [R_0402]  124.09 94.56 180 top
RC325  1K_0402_5%  [R_0402]  134.22 95.55 0 top
RC326  0_0402_5%  [R0402_0OHM]  181.16 100.92 270 top
RC366  0_0402_5%  [R0402_0OHM]  252.22 83.02 270 bottom
RC367  0_0402_5%  [R0402_0OHM]  251.39 83.02 270 bottom
RC368  0_0402_5%  [R0402_0OHM]  250.57 83.02 270 bottom
RC369  0_0402_5%  [R0402_0OHM]  249.74 83.02 270 bottom
RC370  10K_0402_5%  [R_0402]  227.39 110.21 90 top
RC422  0.01_0603_1%  [R_0603-NPM]  178.81 115.9 0 top
RC436  1K_0402_5%  [R_0402]  124.15 99.58 180 top
RC437  1K_0402_5%  [R_0402]  124.09 95.45 180 top
RC438  1K_0402_5%  [R_0402]  128 98.37 180 bottom
RC439  1K_0402_5%  [R_0402]  128 97.55 180 bottom
RC440  1K_0402_5%  [R_0402]  134.22 98.75 0 top
RC441  1K_0402_5%  [R_0402]  124.09 96.34 180 top
RC442  1K_0402_5%  [R_0402]  122.3 92.78 90 top
RC443  1K_0402_5%  [R_0402]  134.22 94.74 0 top
RC557  100K_0402_5%  [R_0402]  243.95 104.66 0 top
RC558  100K_0402_5%  [R_0402]  243.38 104.66 0 bottom
RC559  10K_0402_5%  [R_0402]  207.95 106.37 0 top
RC560  0_0402_5%  [R_0402]  229.34 120.72 0 top
RC561  0_0402_5%  [R_0402]  230.44 116.14 270 top
RC756  10K_0201_5%  [R_0201]  223.64 109.22 90 top
RC834  100K_0402_5%  [R_0402]  225.1 119.34 270 bottom
RC840  10K_0402_5%  [R_0402]  224.28 118.26 270 bottom
RC841  0_0201_5%  [R_0201]  252.83 67.14 225 bottom
RC842  0_0201_5%  [R_0201]  249.53 65.8 225 bottom
RC843  0_0201_5%  [R_0201]  206.93 80.15 225 bottom
RC844  0_0201_5%  [R_0201]  97.59 113.68 270 bottom
RC845  0_0201_5%  [R_0201]  163.25 45.69 180 top
RC846  0_0201_5%  [R_0201]  163.25 45.12 180 top
RC847  0_0201_5%  [R_0201]  277.15 72.26 180 top
RC866  10K_0402_5%  [R_0402]  226.33 119.52 90 bottom
RD4  0_0402_5%  [R_0402]  163.14 47.85 180 top
RD5  0_0402_5%  [R0402_0OHM]  161.43 47.85 180 top
RD6  0_0402_5%  [R_0402]  163.14 46.58 180 top
RD7  0_0402_5%  [R0402_0OHM]  161.43 46.58 180 top
RD8  0_0402_5%  [R_0402]  137.42 43.15 180 top
RD9  0_0402_5%  [R0402_0OHM]  136.51 43.98 0 top
RD10  0_0603_5%  [R0603_0OHM]  163.03 48.84 180 top
RD11  470_0402_1%  [R_0402]  116.63 43.6 0 bottom
RD12  0_0402_5%  [R0402_0OHM]  119.26 43.6 180 bottom
RD14  1K_0402_5%  [R_0402]  126.69 45.31 180 top
RD15  1K_0402_1%  [R_0402]  134.16 45.5 0 top
RD16  1K_0402_1%  [R_0402]  135.06 46.25 90 top
RD17  2_0402_1%  [R_0402]  137.66 45.49 90 top
RD18  24.9_0402_1%  [R_0402]  139.43 45.5 0 top
RD19  330K_0402_5%  [R_0402]  118.28 91.07 0 top
RD20  0_0402_5%  [R_0402]  237.09 45.52 180 top
RD21  0_0402_5%  [R0402_0OHM]  235.31 45.52 180 top
RD22  0_0402_5%  [R0402_0OHM]  237.09 44.7 180 top
RD23  0_0402_5%  [R_0402]  236.21 43.35 0 top
RD24  0_0402_5%  [R_0402]  213.34 42.41 180 top
RD25  0_0402_5%  [R0402_0OHM]  212.42 43.24 0 top
RD26  0_0603_5%  [R0603_0OHM]  237.54 49.31 180 top
RD27  1K_0402_5%  [R_0402]  201.51 43.12 270 top
RD28  1K_0402_1%  [R_0402]  208.94 42.4 90 top
RD29  1K_0402_1%  [R_0402]  209.77 43.32 270 top
RD30  2_0402_1%  [R_0402]  208.12 43.32 270 top
RD31  24.9_0402_1%  [R_0402]  206.34 43.32 270 top
RE5  10K_0402_5%  [R_0402]  273.86 98.24 0 top
RE8  100K_0402_5%  [R_0402]  273.81 93.14 0 top
RE10  100K_0402_5%  [R_0402]  279.26 97.55 0 top
RE11  100K_0402_5%  [R_0402]  257.06 103.96 180 top
RE12  100K_0402_5%  [R_0402]  255.33 93.6 90 bottom
RE20  100K_0402_5%  [R_0402]  247.71 89.81 270 top
RE21  10K_0402_5%  [R_0402]  271.47 104.75 90 top
RE25  100K_0402_5%  [R_0402]  280.17 94.05 180 top
RE26  10_0402_5%  [R_0402]  280.17 93.16 180 top
RE30  0_0402_5%  [R0402_0OHM]  256.24 64.06 180 bottom
RE31  100K_0402_5%  [R_0402]  264.66 110.77 270 top
RE32  0_0402_5%  [R0402_0OHM]  262.04 104.1 180 top
RE33  1K_0402_5%  [R_0402]  263.9 109.85 90 top
RE35  10K_0402_5%  [R_0402]  273.79 90.05 0 top
RE37  2.2K_0402_5%  [R_0402]  260.17 88.9 270 top
RE43  2.2K_0402_5%  [R_0402]  260.99 88.9 270 top
RE48  10K_0402_5%  [R_0402]  91.84 90.63 45 top
RE51  10K_0402_5%  [R_0402]  92.43 90.05 45 top
RE55  100K_0402_5%  [R_0402]  257.06 106.5 180 top
RE56  10K_0402_5%  [R_0402]  252.4 93.99 0 top
RE57  1K_0402_5%  [R_0402]  257.06 104.85 180 top
RE58  100K_0402_5%  [R_0402]  257.06 105.61 180 top
RE59  0_0402_5%  [R0402_0OHM]  282.96 94.82 180 top
RE60  33_0402_5%  [R_0402]  273.81 94.92 0 top
RE63  100K_0402_5%  [R_0402]  276.21 99.58 0 top
RE64  300_0402_5%  [R_0402]  256.17 93.61 180 top
RE65  100_0402_1%  [R_0402]  276.21 97.42 0 top
RE67  10K_0402_5%  [R_0402]  252.99 110.56 180 top
RE68  100K_0402_5%  [R_0402]  253.75 105.61 180 top
RE69  8.2K_0402_5%  [R_0402]  283.83 90.88 0 top
RE70  2.2K_0402_5%  [R_0402]  284.46 94.94 0 top
RE71  10_0402_1%  [R_0402]  263.34 68.9 270 bottom
RE72  10K_0402_5%  [R_0402]  259.22 68.9 270 bottom
RE73  10K_0402_5%  [R_0402]  257.57 68.58 270 bottom
RE74  10K_0402_5%  [R_0402]  256.74 68.58 270 bottom
RE75  100K_0402_5%  [R_0402]  258.39 68.58 270 bottom
RE77  1.69K_0402_1%  [R_0402]  273.86 101.67 0 top
RE79  4.3K_0402_5%  [R_0402]  277.12 94.05 180 top
RE83  100K_0402_5%  [R_0402]  276.21 95.96 0 top
RE84  100K_0402_5%  [R_0402]  276.21 92.06 0 top
RE85  100K_0402_5%  [R_0402]  276.21 91.17 0 top
RE86  10K_0402_5%  [R_0402]  256.24 64.88 180 bottom
RE90  0_0402_5%  [R0402_0OHM]  282.05 95.7 0 top
RE91  100K_0402_5%  [R_0402]  279.26 98.37 0 top
RE92  100K_0402_5%  [R_0402]  253.31 95.51 180 top
RE93  100K_0201_5%  [R_0201]  267.9 105.65 270 top
RE94  75_0402_5%  [R_0402]  268.87 110.06 180 top
RE95  100K_0402_5%  [R_0402]  257.17 100.51 0 top
RE100  0_0201_5%  [R0201_0OHM]  271.33 85.76 90 top
RE274  0_0402_5%  [R_0402]  258.04 91.87 0 top
RE275  0_0402_5%  [R0402_0OHM]  274.71 90.88 180 top
RE280  0_0402_5%  [R_0402]  265.36 123.59 270 top
RE288  100_0402_5%  [R_0402]  273.86 96.34 0 top
RE290  0_0402_5%  [R0402_0OHM]  262.92 103.34 90 top
RE292  0_0402_5%  [R_0402]  263.59 121.35 90 bottom
RE300  33K_0402_5%  [R_0402]  275.66 87.87 90 top
RE301  10K_0402_5%  [R_0402]  272.3 104.75 90 top
RE302  2.2K_0402_5%  [R_0402]  263.81 103.34 90 top
RE303  2.2K_0402_5%  [R_0402]  253.75 104.85 180 top
RE304  0_0402_5%  [R_0402]  261.62 123.98 270 bottom
RE306  0_0402_5%  [R_0402]  255.33 65.71 0 bottom
RE312  300_0402_5%  [R_0402]  257.49 112.55 270 top
RE313  10K_0402_5%  [R_0402]  258.38 112.55 270 top
RE314  100_0402_1%  [R_0402]  256.74 99.06 270 top
RE318  0_0402_5%  [R0402_0OHM]  258.99 96.74 180 top
RE324  100K_0402_5%  [R_0402]  253.75 103.07 180 top
RE340  10K_0402_5%  [R_0402]  255.25 91.83 0 top
RE342  10K_0402_5%  [R_0402]  263.46 86.87 90 top
RE343  130K_0402_5%  [R_0402]  255.67 100.06 180 top
RE349  43K_0402_1%  [R_0402]  261.69 82.65 90 top
RE350  33_0402_5%  [R_0402]  279.27 95.81 0 top
RE362  100K_0402_5%  [R_0402]  257.06 103.07 180 top
RE365  100K_0402_5%  [R_0402]  273.86 99.07 0 top
RE505  100K_0402_5%  [R_0402]  257.06 102.18 180 top
RE506  0_0402_5%  [R0402_0OHM]  257.17 101.33 0 top
RE507  100K_0402_5%  [R_0402]  264.72 104.09 90 top
RE508  100K_0402_5%  [R_0402]  253.75 103.96 180 top
RE509  0_0402_5%  [R0402_0OHM]  274.77 97.42 180 top
RE524  2.2K_0402_5%  [R_0402]  255.71 112.55 270 top
RE525  2.2K_0402_5%  [R_0402]  264.35 107.82 90 top
RE526  10K_0402_5%  [R_0402]  274.77 99.9 180 top
RE529  0_0402_5%  [R_0402]  261.35 86.62 270 top
RE532  4.7K_0402_5%  [R_0402]  274.72 93.97 180 top
RE536  0_0402_5%  [R_0402]  282.96 97.48 180 top
RE539  100_0402_5%  [R_0402]  264.37 122.32 270 bottom
RE541  100K_0402_5%  [R_0402]  285.73 100.85 0 top
RE543  1M_0402_5%  [R_0402]  284.92 100.86 270 top
RE546  10K_0402_5%  [R_0402]  283.4 100.71 90 top
RE548  0_0402_5%  [R0402_0OHM]  251.58 93.85 90 top
RE549  100K_0402_5%  [R_0402]  258.06 90.86 0 top
RE550  100K_0402_5%  [R_0402]  257.51 90.03 180 top
RE551  0_0402_5%  [R_0402]  282.96 98.37 180 top
RE561  100K_0402_5%  [R_0402]  260.87 83.57 270 top
RE565  0_0402_5%  [R0402_0OHM]  277.63 103.35 90 top
RE605  100K_0402_5%  [R_0402]  272.09 86.26 270 top
RE606  100K_0402_5%  [R_0402]  276.21 100.85 0 top
RE702  1M_0402_5%  [R_0402]  256.17 95.39 180 top
RE703  0_0402_5%  [R0402_0OHM]  273.34 87.88 90 top
RE704  10K_0402_5%  [R_0402]  272.45 88.8 270 top
RE706  10K_0402_5%  [R_0402]  279.26 96.72 0 top
RE707  10K_0402_5%  [R_0402]  279.26 92.28 0 top
RE708  10K_0402_5%  [R_0402]  273.81 92.25 0 top
RE712  10K_0402_5%  [R_0402]  260.04 68.9 270 bottom
RE713  10K_0402_5%  [R_0402]  260.87 68.9 270 bottom
RE714  10K_0402_5%  [R_0402]  261.69 68.9 270 bottom
RE715  10K_0402_5%  [R_0402]  262.52 68.9 270 bottom
RE716  100K_0402_5%  [R_0402]  264.47 123.98 270 bottom
RE717  100K_0402_5%  [R_0402]  265.17 87.5 90 top
RE718  100K_0402_5%  [R_0402]  263.58 123.98 270 bottom
RE721  2.2K_0402_5%  [R_0402]  265.49 107.82 90 top
RE722  2.2K_0402_5%  [R_0402]  266.38 107.82 90 top
RE723  100K_0402_5%  [R_0402]  270.24 88.75 0 top
RE724  100K_0402_5%  [R_0402]  270.25 87.96 0 top
RE725  100K_0402_5%  [R_0402]  270.25 87.17 0 top
RE726  100K_0402_5%  [R_0402]  253.31 96.34 180 top
RE727  100K_0402_5%  [R_0402]  256.17 97.17 180 top
RE728  100K_0402_5%  [R_0402]  256.17 96.28 180 top
RE729  100K_0402_5%  [R_0402]  256.17 92.72 180 top
RE730  100K_0402_5%  [R_0402]  256.17 94.5 180 top
RE731  0_0402_5%  [R_0402]  265.68 111.63 90 top
RE821  100K_0402_5%  [R_0402]  282.45 25.17 180 top
RE825  0_0402_5%  [R_0402]  268.51 86.59 90 top
RE826  10K_0402_5%  [R_0402]  266.06 86.01 0 top
RE827  10K_0402_5%  [R_0402]  268.49 89.16 270 top
RE828  0_0201_5%  [R_0201]  269.2 86.5 0 top
RH1  100K_0402_5%  [R_0402]  218.94 103.12 90 top
RH10  0_0201_5%  [R0201_0OHM]  235.64 122.15 90 top
RH11  0_0201_5%  [R0201_0OHM]  234.74 119.82 45 top
RH13  0_0201_5%  [R0201_0OHM]  232.66 123.54 90 top
RH14  0_0201_5%  [R0201_0OHM]  231.01 126.49 90 top
RH15  0_0201_5%  [R0201_0OHM]  228.72 122.49 90 top
RH16  0_0201_5%  [R0201_0OHM]  242.62 101.29 0 bottom
RH28  33_0402_5%  [R_0402]  251.84 92.8 270 top
RH29  33_0402_5%  [R_0402]  249.35 108.6 0 bottom
RH30  20K_0402_5%  [R_0402]  247.91 109.23 180 top
RH37  0_0402_5%  [R0402_0OHM]  252.93 97.04 180 bottom
RH38  30_0402_5%  [R_0402]  204.83 107.52 0 top
RH39  30_0402_5%  [R_0402]  204.83 106.69 0 top
RH42  30_0402_5%  [R_0402]  208.99 104.98 180 top
RH43  0_0402_5%  [R0402_0OHM]  244.79 112.67 270 bottom
RH44  10M_0402_5%  [R_0402]  244.03 111.76 90 bottom
RH45  33_0402_5%  [R_0402]  219.39 127.59 270 top
RH46  33_0402_5%  [R_0402]  219.4 122.76 180 top
RH48  33_0402_5%  [R_0402]  220.33 122.76 0 top
RH50  33_0402_5%  [R_0402]  217.61 126.71 270 top
RH56  1K_0402_5%  [R_0402]  230.83 121.97 180 bottom
RH57  1K_0402_5%  [R_0402]  228.14 121.93 0 bottom
RH61  4.7K_0201_5%  [R_0201]  227.68 119.2 180 bottom
RH62  0_0402_5%  [R0402_0OHM]  225.85 133.36 0 top
RH65  100K_0201_5%  [R_0201]  230.06 133.12 270 top
RH66  0_0402_5%  [R0402_0OHM]  210.99 119.83 0 top
RH67  499_0402_1%  [R_0402]  229.37 116.28 180 top
RH70  8.2K_0402_5%  [R_0402]  208.47 121.63 270 top
RH73  13_0402_5%  [R_0402]  207.26 102.26 270 bottom
RH74  10K_0402_5%  [R_0402]  208.14 101.8 0 bottom
RH75  620_0402_5%  [R_0402]  208.1 99.71 180 bottom
RH76  10K_0402_5%  [R_0402]  244.86 105.42 180 top
RH77  499_0402_1%  [R_0402]  227.72 117.2 180 top
RH78  4.7K_0201_5%  [R_0201]  229.08 115.49 180 top
RH80  1K_0402_5%  [R_0402]  227.5 120.98 0 top
RH81  1K_0402_5%  [R_0402]  226.68 119.64 0 top
RH83  1K_0402_5%  [R_0402]  239.31 110.75 0 top
RH86  4.7K_0201_5%  [R_0201]  232.05 117.49 0 top
RH90  10K_0402_5%  [R_0402]  214.63 127.59 270 top
RH92  1K_0402_5%  [R_0402]  243.45 115.12 90 bottom
RH93  10K_0402_5%  [R_0402]  238.88 115 90 top
RH94  8.2K_0402_5%  [R_0402]  239.64 115 90 top
RH95  10K_0402_5%  [R_0402]  235.07 112.99 270 top
RH97  33_0402_5%  [R_0402]  247.96 83.02 270 bottom
RH100  0_0402_5%  [R0402_0OHM]  284.54 61.28 90 bottom
RH101  1K_0402_5%  [R_0402]  284.54 64.03 270 bottom
RH104  10K_0402_5%  [R_0402]  251 101.23 0 top
RH110  10K_0201_5%  [R_0201]  218.04 95.69 90 top
RH123  10K_0201_5%  [R_0201]  235.01 122.15 90 top
RH124  10K_0201_5%  [R_0201]  234.25 119.17 270 top
RH125  10K_0201_5%  [R_0201]  232.47 126.46 90 top
RH126  10K_0201_5%  [R_0201]  233.32 124.22 0 top
RH127  10K_0201_5%  [R_0201]  231.77 126.46 90 top
RH131  10K_0201_5%  [R_0201]  228 122.47 180 top
RH132  10K_0201_5%  [R_0201]  242.53 100.34 0 bottom
RH133  10K_0201_5%  [R_0201]  242.59 98.07 0 bottom
RH152  0_0201_5%  [R_0201]  213.77 96.09 180 bottom
RH153  1M_0402_1%  [R_0402]  212.47 95.25 90 bottom
RH154  0_0201_5%  [R_0201]  211.49 98.7 180 top
RH155  0_0201_5%  [R_0201]  211.49 97.94 180 top
RH156  30_0402_5%  [R_0402]  209.05 100.98 180 bottom
RH161  0_0402_5%  [R0402_0OHM]  213.55 81.34 90 bottom
RH166  0_0402_5%  [R0402_0OHM]  212.72 81.34 90 bottom
RH167  0_0402_5%  [R0402_0OHM]  210.05 82.26 270 bottom
RH168  0_0402_5%  [R0402_0OHM]  209.23 82.26 270 bottom
RH169  0_0402_5%  [R0402_0OHM]  211.7 81.34 90 bottom
RH170  0_0402_5%  [R0402_0OHM]  210.88 81.34 90 bottom
RH177  0_0402_5%  [R_0402]  232.71 129.17 0 bottom
RH178  4.99_0402_1%  [R_0402]  233.79 128.22 0 bottom
RH179  4.99_0402_1%  [R_0402]  235 129.17 0 bottom
RH180  0_0402_5%  [R_0402]  247.01 107.5 90 top
RH181  4.99_0402_1%  [R_0402]  236.27 128.34 0 bottom
RH182  0_0402_5%  [R_0402]  237.47 129.17 0 bottom
RH183  4.99_0402_1%  [R_0402]  238.68 128.34 0 bottom
RH184  4.99_0402_1%  [R_0402]  239.89 129.17 0 bottom
RH185  0_0402_5%  [R_0402]  243.02 128.6 180 bottom
RH187  0_0402_5%  [R0402_0OHM]  229.97 134.1 180 top
RH192  100_0402_1%  [R_0402]  216.53 81.47 90 bottom
RH193  113_0402_1%  [R_0402]  212.92 87.7 180 bottom
RH198  1M_0402_5%  [R_0402]  243.53 109.55 180 top
RH199  100K_0402_5%  [R_0402]  210.1 112.98 0 top
RH200  20K_0402_5%  [R_0402]  244.34 110.2 270 top
RH201  20K_0402_5%  [R_0402]  243.53 110.31 180 top
RH203  10K_0201_5%  [R_0201]  233.99 122.11 90 bottom
RH204  10K_0201_5%  [R_0201]  237.88 120.91 180 bottom
RH214  100K_0402_5%  [R_0402]  215.45 127.59 270 top
RH215  0_0402_5%  [R0402_0OHM]  241.49 112.84 90 top
RH221  2.2K_0402_5%  [R_0402]  217.5 103.01 180 top
RH222  2.2K_0402_5%  [R_0402]  217.5 104.72 180 top
RH223  2.2K_0402_5%  [R_0402]  217.5 105.55 180 top
RH224  2.2K_0402_5%  [R_0402]  217.5 103.83 180 top
RH225  2.2K_0402_5%  [R_0402]  210.1 112.15 0 top
RH237  0_0402_5%  [R0402_0OHM]  231.21 103.04 180 top
RH238  0_0603_5%  [R_0603-NPM]  212.97 90.75 180 top
RH239  0_0603_5%  [R_0603]  223.71 112.25 180 top
RH240  0_0402_5%  [R0402_0OHM]  217.93 84.52 90 top
RH241  0_0603_5%  [R_0603]  214.63 87.45 90 top
RH242  0_0603_5%  [R0603_0OHM]  221.07 113.49 0 top
RH243  10K_0402_5%  [R_0402]  238.81 118.25 0 bottom
RH246  0_0402_5%  [R0402_0OHM]  243.4 102.94 180 top
RH247  0_0603_5%  [R_0603]  219.9 116.06 270 top
RH250  0_0402_5%  [R_0402]  243.4 103.77 180 top
RH254  0_1206_5%  [R_1206]  207.58 84.27 0 top
RH255  0_0402_5%  [R_0402]  240.8 115.71 180 bottom
RH256  0_0402_5%  [R0402_0OHM]  237.63 98.56 180 top
RH257  0_0402_5%  [R0402_0OHM]  221.29 98.17 90 top
RH258  0_0402_5%  [R0402_0OHM]  223.71 98.05 0 top
RH259  0_0402_5%  [R0402_0OHM]  209.23 85.66 270 bottom
RH260  0_0402_5%  [R0402_0OHM]  223.9 96.09 0 top
RH267  10K_0201_5%  [R_0201]  230.56 122.4 90 top
RH268  10K_0201_5%  [R_0201]  229.89 121.68 0 top
RH279  0_1206_5%  [R_1206]  245.36 92.09 180 top
RH286  0_0402_5%  [R0402_0OHM]  226.73 93.83 90 top
RH287  0_0402_5%  [R0402_0OHM]  237.63 99.32 180 top
RH288  0_0402_5%  [R0402_0OHM]  237.63 100.09 180 top
RH289  0_0603_5%  [R_0603-NPM]  242.37 87.77 0 top
RH290  0_0402_5%  [R0402_0OHM]  241.17 91.37 90 top
RH291  0_0402_5%  [R_0402]  232.28 111.44 270 top
RH292  0_0402_5%  [R0402_0OHM]  219.95 119.39 0 top
RH293  0_0402_5%  [R0402_0OHM]  226.38 111.98 90 top
RH294  0_0402_5%  [R0402_0OHM]  233.66 112.49 270 top
RH295  0_0402_5%  [R_0402]  219.51 118.6 0 top
RH296  0_0402_5%  [R_0402]  225.61 114.87 270 top
RH297  0_0402_5%  [R0402_0OHM]  243.85 112.41 180 top
RH298  0_0402_5%  [R0402_0OHM]  217.61 116.16 270 top
RH299  0_0402_5%  [R0402_0OHM]  218.73 114.07 315 top
RH300  0_0402_5%  [R0402_0OHM]  243.14 106.51 270 top
RH302  0_0402_5%  [R0402_0OHM]  243.95 106.25 0 top
RH303  0_0402_5%  [R0402_0OHM]  243.4 101.8 180 top
RH304  0_0402_5%  [R0402_0OHM]  231.39 111.44 270 top
RH305  0_0402_5%  [R0402_0OHM]  226.38 111.12 270 top
RH306  0_0402_5%  [R0402_0OHM]  237.17 96.84 90 top
RH308  100K_0402_5%  [R_0402]  240.66 112.8 270 top
RH309  10K_0201_5%  [R_0201]  228.34 111.12 270 top
RH310  10K_0402_5%  [R_0402]  248.1 102.25 180 top
RH311  8.2K_0201_5%  [R_0201]  230.76 112.86 270 top
RH312  51_0402_5%  [R_0402]  207.65 104.09 180 top
RH313  51_0402_5%  [R_0402]  215.15 101.36 180 top
RH314  51_0402_5%  [R_0402]  207.46 101.86 180 top
RH315  51_0402_5%  [R_0402]  207.72 104.15 180 bottom
RH316  10K_0201_5%  [R_0201]  245.82 101.42 180 top
RH317  10K_0402_5%  [R_0402]  242.63 98.74 90 bottom
RH318  10K_0402_5%  [R_0402]  243.45 98.74 90 bottom
RH319  10K_0402_5%  [R_0402]  209.55 109.75 270 top
RH323  10K_0402_5%  [R_0402]  244.29 106.18 180 bottom
RH324  10K_0402_5%  [R_0402]  245.82 102.25 180 top
RH325  10K_0402_5%  [R_0402]  235.38 104.28 0 top
RH326  10K_0402_5%  [R_0402]  244.29 105.42 180 bottom
RH328  1K_0402_5%  [R_0402]  218.49 125.87 0 top
RH329  150K_0402_5%  [R_0402]  232.53 115.89 90 top
RH331  4.7K_0402_5%  [R_0402]  233.17 123.02 270 bottom
RH333  2.2K_0402_5%  [R_0402]  227.65 123.1 90 bottom
RH334  1K_0402_5%  [R_0402]  247.91 110.88 180 top
